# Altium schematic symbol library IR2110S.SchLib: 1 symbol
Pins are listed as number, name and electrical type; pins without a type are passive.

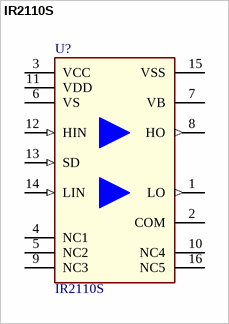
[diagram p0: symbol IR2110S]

## IR2110S
designator U?
High and Low Side Driver; Manufacturer: Infineon Technologies
pins: 1 LO (out) "Low side gate drive output", 2 COM (power) "Low side return", 3 VCC (power) "Low side supply", 4 NC1 "No Connection", 5 NC2 "No Connection", 6 VS (power) "High side floating supply return", 7 VB (power) "High side floating supply", 8 HO (out) "High side gate drive output", 9 NC3 "No Connection", 10 NC4 "No Connection", 11 VDD (power) "Logic Supply", 12 HIN (in) "Logic input for high side gate driver outputs (HO), in phase", 13 SD (in) "Logic input for shutdown", 14 LIN (in) "Logic input for low side gate driver outputs (LO), in phase", 15 VSS (power) "Logic ground", 16 NC5 "No Connection"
